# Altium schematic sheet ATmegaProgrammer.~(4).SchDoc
size A4
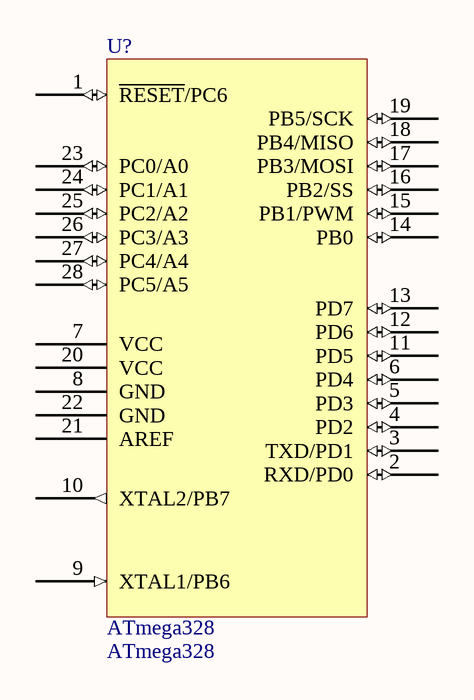
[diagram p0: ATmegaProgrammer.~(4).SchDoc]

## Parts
U?  ATmega328  [DIP28]

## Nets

Not connected (* = marked no-connect by the designer): U? 1(~{RESET}/PC6) 2(RXD/PD0) 3(TXD/PD1) 4(PD2) 5(PD3) 6(PD4) 7(VCC) 8(GND) 9(XTAL1/PB6) 10(XTAL2/PB7) 11(PD5) 12(PD6) 13(PD7) 14(PB0) 15(PB1/PWM) 16(PB2/SS) 17(PB3/MOSI) 18(PB4/MISO) 19(PB5/SCK) 20(VCC) 21(AREF) 22(GND) 23(PC0/A0) 24(PC1/A1) 25(PC2/A2) 26(PC3/A3) 27(PC4/A4) 28(PC5/A5)

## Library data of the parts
U? = ATmega328: ATmega╰�C虫垂��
